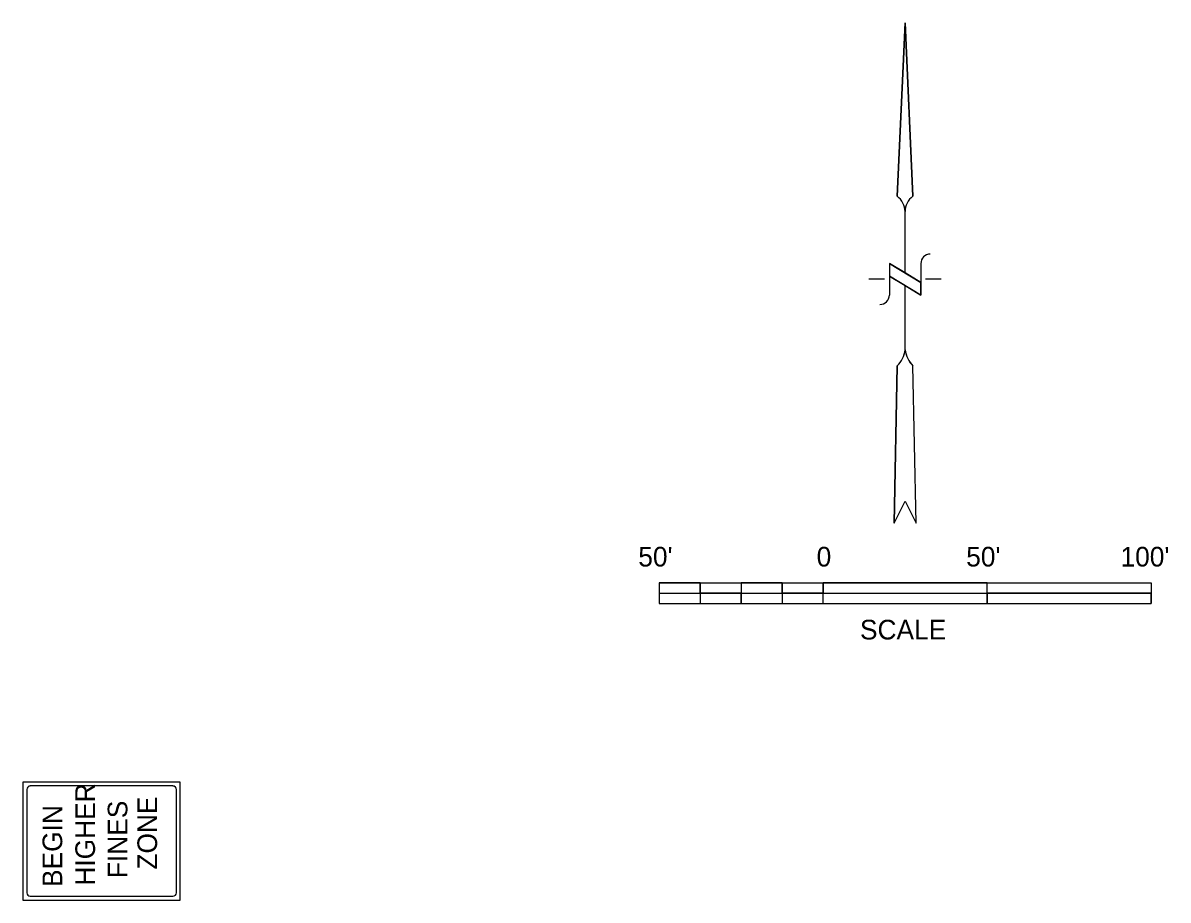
# Model space of a CAD drawing. Extents: x 2155255 to 2162649, y 140388 to 141878.
# Drawn here: x 2155765.7 to 2156114.9, y 141231.4 to 141499 of the extents above; entities that cross this region are included whole.
import ezdxf

# ---------------------------------------------------------------- set-up
doc = ezdxf.new("R2010")
doc.units = 0
for name, color, linetype in [('Default', 7, 'Continuous'), ('PR_Traffic_Control_Devices_Temp', 7, 'Continuous'), ('SHT_North_Arrow', 7, 'Continuous'), ('SHT_Scale', 7, 'Continuous')]:
    doc.layers.add(name, color=color, linetype=linetype)

# ---------------------------------------------------------------- blocks, each defined once
blk = doc.blocks.new('R2-10')
at = {"layer": 'Default'}
for p, q in [((3, 4), (0, 4)), ((0, 4), (0, 0)), ((0.1, 3.812), (0.1, 0.187)), ((2.812, 3.9), (0.187, 3.9)), ((2.9, 0.187), (2.9, 3.812)), ((3, 0), (3, 4)), ((0, 0), (3, 0)), ((0.187, 0.1), (2.812, 0.1))]:
    blk.add_line(p, q, dxfattribs=at)
for centre, start, end in [((0.187, 3.812), 90, 180), ((2.812, 3.812), 0, 90), ((0.187, 0.187), 180, 270), ((2.812, 0.187), 270, 0)]:
    blk.add_arc(centre, 0.0875, start, end, dxfattribs=at)
for s, p in [('BEGIN', (0.333, 3)), ('HIGHER', (0.367, 2.167)), ('FINES', (0.558, 1.344)), ('ZONE', (0.775, 0.59))]:
    blk.add_text(s, height=0.5, dxfattribs=at).set_placement(p)

msp = doc.modelspace()

# ---------------------------------------------------------------- linework, layer by layer
at = {"layer": 'SHT_North_Arrow'}
for p, q in [((2156032.32, 141446.09), (2156034.72, 141498.98)), ((2156034.72, 141498.98), (2156032.32, 141446.09)), ((2156034.72, 141498.98), (2156037.12, 141446.09)), ((2156037.12, 141446.09), (2156034.72, 141498.98)), ((2156034.72, 141422.7), (2156034.72, 141441.41)), ((2156039.52, 141419.82), (2156029.92, 141425.57)), ((2156029.92, 141425.57), (2156039.52, 141419.82)), ((2156029.92, 141425.57), (2156029.92, 141415.98)), ((2156034.72, 141422.7), (2156029.92, 141425.57)), ((2156029.92, 141425.57), (2156029.92, 141421.74)), ((2156039.52, 141425.57), (2156039.52, 141415.98)), ((2156039.52, 141415.98), (2156029.92, 141421.74)), ((2156039.52, 141419.82), (2156034.72, 141422.7)), ((2156028.48, 141420.78), (2156023.69, 141420.78)), ((2156034.72, 141399.19), (2156034.72, 141418.86)), ((2156039.52, 141415.98), (2156039.52, 141419.82)), ((2156045.75, 141420.78), (2156040.96, 141420.78)), ((2156031.36, 141346.42), (2156032.32, 141394.39)), ((2156032.32, 141394.39), (2156031.36, 141346.42)), ((2156038.08, 141346.42), (2156037.12, 141394.39)), ((2156038.08, 141346.42), (2156037.12, 141394.39)), ((2156031.36, 141346.42), (2156034.72, 141353.13)), ((2156031.36, 141346.42), (2156034.72, 141353.13)), ((2156034.72, 141353.13), (2156038.08, 141346.42)), ((2156034.72, 141353.13), (2156038.08, 141346.42))]:
    msp.add_line(p, q, dxfattribs=at)
for points in [[(2156029.92, 141421.74), (2156034.72, 141418.86), (2156039.52, 141415.98)], [(2156034.73, 141399.19), (2156034.72, 141399.19), (2156034.71, 141399.19)]]:
    msp.add_lwpolyline(points, dxfattribs=at)
for centre, radius, start, end in [((2156028.96, 141441.41), 5.76, 0, 54.3802), ((2156028.96, 141441.41), 5.76, 0, 54.3802), ((2156040.48, 141441.41), 5.76, 125.6198, 180), ((2156040.48, 141441.41), 5.76, 125.6198, 180), ((2156042.4, 141425.57), 2.88, 90, 180), ((2156027.04, 141415.98), 2.88, 270, 0), ((2156026.37, 141400.35), 8.43, 314.9567, 352.4189), ((2156026.37, 141400.35), 8.43, 314.9567, 352.059), ((2156043.07, 141400.35), 8.43, 187.5811, 225.0433), ((2156043.07, 141400.35), 8.43, 187.941, 225.0433)]:
    msp.add_arc(centre, radius, start, end, dxfattribs=at)
at = {"layer": 'SHT_Scale'}
for p, q in [((2155959.72, 141328.17), (2155959.72, 141321.92)), ((2155959.72, 141328.17), (2156109.72, 141328.17)), ((2155959.72, 141328.17), (2155959.72, 141325.05)), ((2155972.22, 141328.17), (2155959.72, 141328.17)), ((2155972.22, 141328.17), (2155972.22, 141321.92)), ((2155972.22, 141325.05), (2155972.22, 141328.17)), ((2155984.72, 141328.17), (2155984.72, 141321.92)), ((2155984.72, 141328.17), (2155984.72, 141321.92)), ((2155984.72, 141328.17), (2155984.72, 141325.05)), ((2155997.22, 141328.17), (2155984.72, 141328.17)), ((2155997.22, 141328.17), (2155997.22, 141321.92)), ((2155997.22, 141325.05), (2155997.22, 141328.17)), ((2156009.72, 141325.05), (2156009.72, 141328.17)), ((2156009.72, 141328.17), (2156009.72, 141325.05)), ((2156059.72, 141328.17), (2156009.72, 141328.17)), ((2156059.72, 141325.05), (2156059.72, 141328.17)), ((2156059.72, 141325.05), (2156059.72, 141328.17)), ((2156109.72, 141328.17), (2156109.72, 141325.05)), ((2155959.72, 141325.05), (2155972.22, 141325.05)), ((2155959.72, 141325.05), (2155972.22, 141325.05)), ((2155972.22, 141325.05), (2155984.72, 141325.05)), ((2155984.72, 141325.05), (2155972.22, 141325.05)), ((2155972.22, 141325.05), (2155972.22, 141321.92)), ((2155984.72, 141325.05), (2155997.22, 141325.05)), ((2155984.72, 141321.92), (2155984.72, 141325.05)), ((2155984.72, 141325.05), (2155997.22, 141325.05)), ((2155997.22, 141325.05), (2156009.72, 141325.05)), ((2156009.72, 141325.05), (2155997.22, 141325.05)), ((2155997.22, 141325.05), (2155997.22, 141321.92)), ((2156009.72, 141321.92), (2156009.72, 141325.05)), ((2156009.72, 141325.05), (2156109.72, 141325.05)), ((2156009.72, 141321.92), (2156009.72, 141325.05)), ((2156009.72, 141325.05), (2156059.72, 141325.05)), ((2156059.72, 141321.92), (2156059.72, 141325.05)), ((2156109.72, 141325.05), (2156059.72, 141325.05)), ((2156059.72, 141325.05), (2156059.72, 141321.92)), ((2156109.72, 141325.05), (2156109.72, 141321.92)), ((2156109.72, 141321.92), (2156109.72, 141325.05)), ((2155959.72, 141321.92), (2156109.72, 141321.92)), ((2155972.22, 141321.92), (2155984.72, 141321.92)), ((2155997.22, 141321.92), (2156009.72, 141321.92)), ((2156059.72, 141321.92), (2156109.72, 141321.92))]:
    msp.add_line(p, q, dxfattribs=at)

# ---------------------------------------------------------------- block references
at = {"layer": 'PR_Traffic_Control_Devices_Temp', "xscale": 12, "yscale": 12, "rotation": 90}
msp.add_blockref('R2-10', (2155813.68, 141231.43), dxfattribs=at)

# ---------------------------------------------------------------- texts
at = {"layer": 'SHT_Scale'}
for s, p in [("50'", (2155953.36, 141333.17)), ('0', (2156007.75, 141333.17)), ("50'", (2156053.36, 141333.17)), ("100'", (2156100.42, 141333.17)), ('SCALE', (2156020.96, 141310.92))]:
    msp.add_text(s, height=6, dxfattribs=at).set_placement(p)

doc.saveas('drawing.dxf')
